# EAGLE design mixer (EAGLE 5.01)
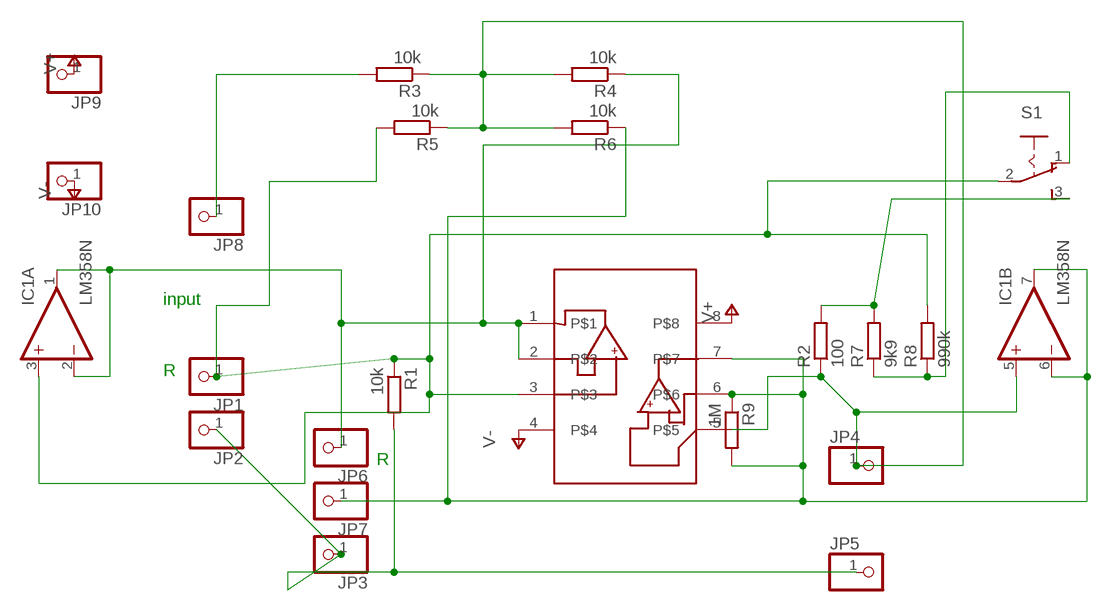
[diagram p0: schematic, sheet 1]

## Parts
IC1  LM358N  [DIL08]
JP1  PINHD-1X1  [1X01]
JP2  PINHD-1X1  [1X01]
JP3  PINHD-1X1  [1X01]
JP4  PINHD-1X1  [1X01]
JP5  PINHD-1X1  [1X01]
JP6  PINHD-1X1  [1X01]
JP7  PINHD-1X1  [1X01]
JP8  PINHD-1X1  [1X01]
JP9  PINHD-1X1  [1X01]
JP10  PINHD-1X1  [1X01]
R1  10k  R-EU_0207/10  [0207/10]
R2  100  R-EU_0207/10  [0207/10]
R3  10k  R-EU_0207/10  [0207/10]
R4  10k  R-EU_0207/10  [0207/10]
R5  10k  R-EU_0207/10  [0207/10]
R6  10k  R-EU_0207/10  [0207/10]
R7  9k9  R-EU_0207/10  [0207/10]
R8  990k  R-EU_0207/10  [0207/10]
R9  1M  R-EU_0204/7  [0204/7]
S1  255SB  [255SB]
U$1  MCP6042SOIC  [SO-08]

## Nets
GND: JP2.1 JP3.1 JP5.1 R1.2
IN_L: JP8.1 R3.2
IN_R: IC1.3(A:+IN) JP1.1 R1.1 R5.2 R8.2 S1.2(P) U$1.3
N$3: R2.2 R7.2 S1.3(S)
N$7: R7.1 R8.1 S1.1(O)
N$8: IC1.5(B:+IN) JP4.1 R2.1 R3.1 R4.2 R5.1 R6.2 U$1.5
OUT_L: IC1.6(B:-IN) IC1.7(B:OUT) JP7.1 R6.1 R9.1 R9.2 U$1.6 U$1.7
OUT_R: IC1.1(A:OUT) IC1.2(A:-IN) JP6.1 R4.1 U$1.1 U$1.2
V+: JP9.1 U$1.8
V-: JP10.1 U$1.4

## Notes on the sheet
- input
- R
- R

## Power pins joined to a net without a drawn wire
V+: IC1.8(P:V+)
V-: IC1.4(P:V-)

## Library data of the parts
IC1 = linear4:LM358: OP AMP
JP1-JP10 = pinhead:PINHD-1X1: PIN HEADER
R1-R9 = rcl-2:R-EU_: RESISTOR, European symbol
S1 = switch:255SB: SLIDING SWITCH distributor Buerklin, 11G810
U$1 = microchip-3:MCP6042

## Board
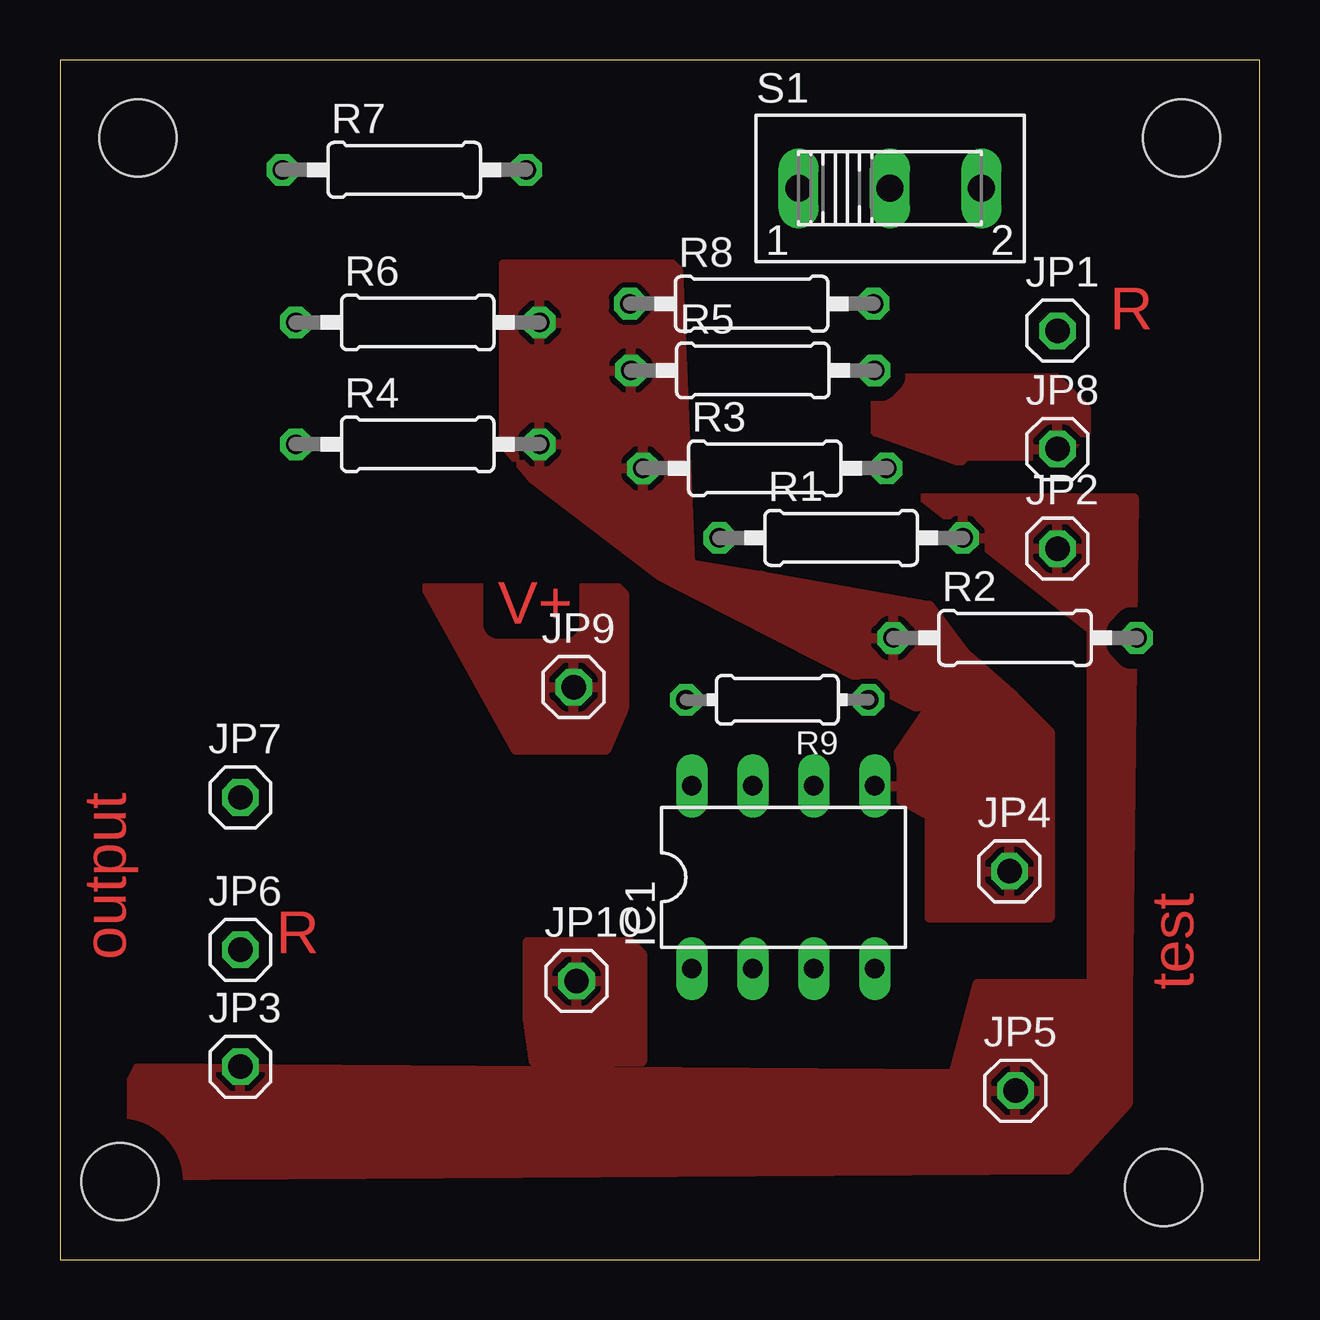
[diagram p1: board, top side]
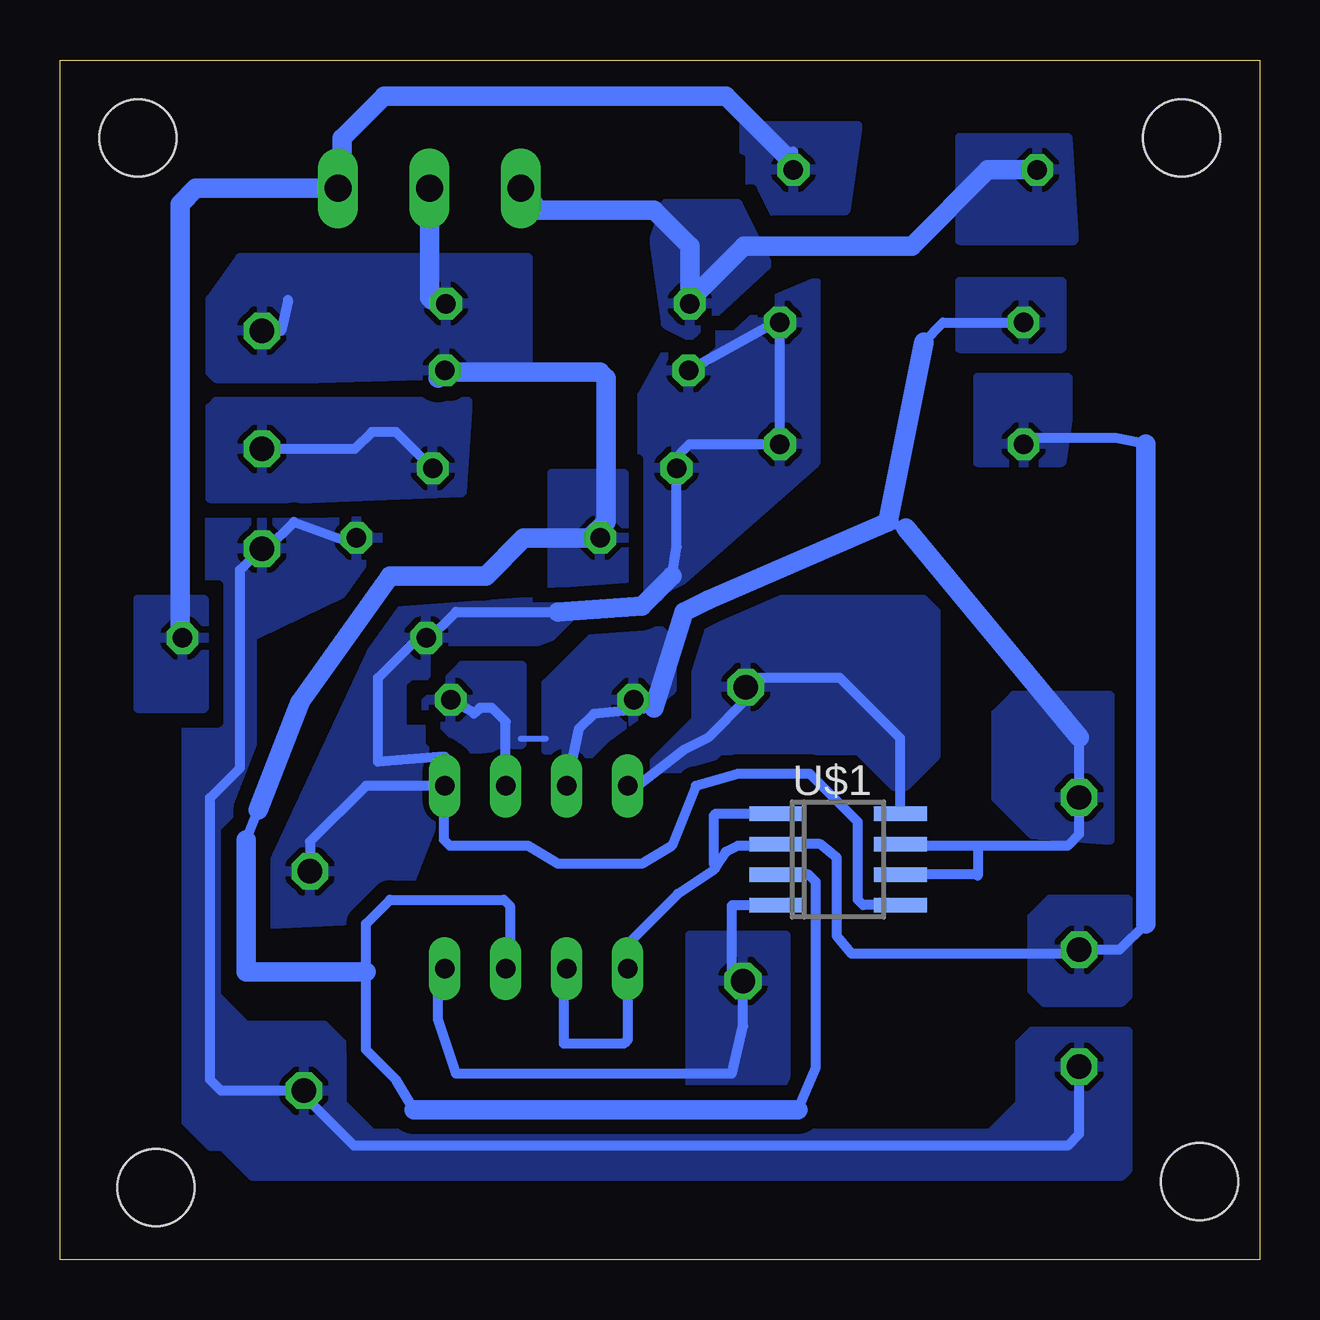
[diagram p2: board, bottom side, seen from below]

Size 50 x 50 mm. Coordinates in mm from the lower left corner, seen from the top.
Outline: 0,0 50,0 50,50 0,50 0,0
Copper layers (1*16): Top 0.035mm / dielectric 1.5mm / Bottom 0.035mm
Design rules "default *": minimum track width 10mil, minimum drill 24mil, track to track 8mil, track to pad 8mil, pad to pad 8mil, via to via 8mil, smd to smd 8mil, copper to edge 40mil, drill to drill 8mil, minimum pad ring 10mil, minimum via ring 8mil, stop-mask expansion 4mil, vias tented up to drill 0mil, thermal gap 10mil
Holes 3.2 mm at 46.75,46.75 46,3 2.5,3.25 3.25,46.75

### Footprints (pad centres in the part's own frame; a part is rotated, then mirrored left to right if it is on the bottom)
DIL08 = drill 0.813 long: 1 -3.81,-3.81; 2 -1.27,-3.81; 3 1.27,-3.81; 4 3.81,-3.81; 5 3.81,3.81; 6 1.27,3.81; 7 -1.27,3.81; 8 -3.81,3.81
1X01 = drill 1.016 octagon: 1 0,0
0207/10 = drill 0.813 octagon: 1 -5.08,0; 2 5.08,0
0204/7 = drill 0.813 octagon: 1 -3.81,0; 2 3.81,0
255SB = drill 1.118 long: 1 -3.81,0; 2 0,0; 3 3.81,0
SO-08 = smd 0.6 x 2.2: 1 -1.905,-2.6; 2 -0.635,-2.6; 3 0.635,-2.6; 4 1.905,-2.6; 5 1.905,2.6; 6 0.635,2.6; 7 -0.635,2.6; 8 -1.905,2.6

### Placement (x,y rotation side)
IC1  30.15,15.93 0 top
JP1  41.58,38.71 0 top
JP2  41.58,29.63 0 top
JP3  7.52,8.04 0 top
JP4  39.58,16.18 0 top
JP5  39.83,7.04 0 top
JP6  7.52,12.91 0 top
JP7  7.52,19.26 0 top
JP8  41.58,33.79 0 top
JP9  21.41,23.86 0 top
JP10  21.53,11.61 0 top
R1  32.56,30.08 0 top
R2  39.81,25.91 0 top
R3  29.38,32.98 0 top
R4  14.91,33.98 0 top
R5  28.88,37.06 0 top
R6  14.91,39.06 0 top
R7  14.35,45.42 0 top
R8  28.83,39.84 0 top
R9  29.9,23.33 180 top
S1  34.6,44.65 0 top
U$1  17.57,16.68 270 bottom

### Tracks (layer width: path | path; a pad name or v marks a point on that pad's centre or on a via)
GND
  Bottom 0.406: JP3.1 7.52,5.23 8,4.75 37.75,4.75 40,7 39.96,7.04 JP5.1 43.29,7.04 43.75,7.5 43.75,19.25 42.5,20.5 42.5,28.75 41.62,29.63 JP2.1 41.37,29.63 40.25,30.75 37.5,29.75 37.64,29.89 R1.2
  pour Top (isolate 0.61, rank 2): 43,11.5 43,26.25 36,31.75 44.75,31.75 44.5,11 44.5,6.5 42,3.75 3,3.5 3,7.5 3.25,8 37.25,7.75 38.25,11.5
  pour Bottom (isolate 0.61, rank 3): 5.5,9.5 9.5,9.5 10,9 10,6.5 11.25,5.25 37,5.25 38.25,6.5 38.25,9 39,9.75 42.25,9.75 43.5,11 43.5,18 42,19.5 42,26 36.75,28.5 36.75,30.75 44.75,31.75 44.75,28.75 43.75,27.75 43.75,24.25 44.75,23.25 44.75,5.75 43.75,4.75 43.25,4.75 42,3.5 5.75,3.5 5.5,3.75
IN_L
  Bottom 0.406: JP8.1 37.71,33.79 37,34.5 36,34.5 34.46,32.96 | 34.46,32.96 34.25,32.75 | R3.2 34.46,32.96
  pour Bottom (isolate 0.61): 33,35.75 43.5,35.75 43.75,35.5 43.75,31.75 39.5,31.75 33.25,32
  pour Top (isolate 0.61, rank 2): 34,34.5 34,36.25 34.5,36.75 41.5,36.75 42.75,35.5 42.75,34.5 41.75,33.5 41.5,33.5 37.75,33.5 37.5,33.25
IN_R
  Bottom 0.406: U$1.3 18.8,16.05 18.5,15.75 18.5,8 19.25,6.25 | 35.25,6.25 36,7.5 37.25,8.75 37.25,12 37.25,14 36.25,15 31.5,15 31.25,14.75 31.25,12.5 31.5,12.25 31.42,12.17 IC1.3 | JP1.1 40.79,38.71 40.5,40 | 30.67,30.08 R1.1 | 42.25,17.5 41.75,18.75
  Bottom 0.813: 19.25,6.25 35.25,6.25 | 41.75,18.75 40,23.25 36.25,28.5 32.25,28.5 30.67,30.08 27.92,30.08 27.25,30.75 27.25,36.75 27.5,37 34,37 | 42.25,17.5 42.25,12 37.25,12 | 34,37 33.96,37.04 R5.2 | 34,37 34.25,36.75 | S1.2 34.6,40.1 34.5,40 34,40 33.91,39.91 R8.2
  pour Bottom (isolate 0.61): 30.5,41.75 42.5,41.75 43.75,40 43.75,37 43.5,36.75 39.25,36.75 30.5,37
  pour Bottom (isolate 0.61): 26.5,32.75 29.5,32.75 29.5,28 26.5,28
N$3
  Bottom 0.406: R7.2 19.43,46.18 | 45,25.75 44.89,25.86 R2.2
  Bottom 0.813: 45,40 45,25.75 | 45,40 45,41 | R7.2 19.43,45.68 22.25,48.5 36.5,48.5 38.25,46.75 38.25,45.25 38.5,45 38.41,44.91 S1.3 44.35,44.65 45,44 45,40
  pour Bottom (isolate 0.61, rank 2): 44,27.5 46.75,27.5 46.75,27.25 46.75,23 44,23 44,23.25
  pour Bottom (isolate 0.61, rank 2): 16.75,47.25 21.5,47.25 21.5,46.25 21.25,46.25 21.25,43.75 17.25,43.75
N$7
  Bottom 0.813: R7.1 11.33,45.42 14.5,42.25 21.5,42.25 23.75,40 R8.1 23.75,42.25 25.25,43.75 30.25,43.75 30.25,44 30.79,44.54 S1.1
  pour Bottom (isolate 0.61): 20.5,41.5 21.75,44 24.75,44 25.25,42.5 24.75,39 23.75,38.5
  pour Bottom (isolate 0.61, rank 2): 8,46.75 12.5,46.75 12.5,42.5 7.75,42.5 7.75,42.75
N$8
  Bottom 0.406: U$1.5 16.52,14.78 16.75,15 16.75,18.25 18.75,20.25 21.75,20.25 23.5,19.75 24.5,17.25 25.75,16.5 29.25,16.5 30.5,17.25 33.75,17.25 34,17.5 34,19.25 34.25,19.5 34.01,19.74 IC1.5 | R5.1 20.19,39.06 20,39.25 19.99,39.24 R6.2 R4.2 | R4.2 19.99,33.76 20,33.75 | R4.2 23.77,33.98 24.5,33.25 24.3,33.05 R3.1 24.3,29.7 24.5,28.5 | 34.73,25.77 34.75,25.75 | 34.73,25.77 R2.1 34.73,26.23 34.75,26.25 36.75,24.25 36.75,20.75 33.96,20.96 IC1.5 | 29.25,27 33.5,27 34.73,25.77 | JP4.1 39.58,17.42 37.25,19.75 33.75,19.75 33.76,19.74 IC1.5
  Bottom 0.813: 24.5,28.5 25.75,27.25 29.25,27
  pour Top (isolate 0.61): 37.75,25.25 39.75,23.5 41.25,22 41.25,14.25 36.25,14.25 36.25,18.5 34,19.75
  pour Top: 18.5,41.5 25.5,41.5 25.75,41.25 26.25,29 29.25,28.5 36.25,27.25 37.75,25.25 35.75,23 25,28.5 19.75,32.5 18.5,34
  pour Bottom (isolate 0.61, rank 2): 18.5,40.75 24.5,38.25 25.75,36 25.75,29 26,27.75 36.25,27 41.25,16.25 41.25,14 36,14.25 33.75,20 35.25,23.25 34.25,24.25 24.75,27.75 18.5,33.25
OUT_L
  Bottom 0.254: 29.75,21.7 30.8,21.7
  Bottom 0.406: 7.52,21.77 JP7.1 7.52,17.73 8,17.25 11.75,17.25 | 14.75,30.5 15.5,30.75 | IC1.7 28.38,22.12 27.75,22.75 25.25,23 25.17,23.08 R9.2 | IC1.6 31.42,22.42 32,23 32.5,23 32.71,22.79 | 32.71,22.79 32.75,22.75 | 32.71,22.79 R9.1 | R6.1 13.19,39.06 14,38.25 | U$1.7 14.56,17.32 14.5,17.25 11.75,17.25 | U$1.6 11.79,16.05 11.75,16 11.75,17.25
  Bottom 0.813: 7.52,21.77 14.75,30.5 | 25.25,23 24,27 23,27.5 15.5,30.75 14,38.25
  pour Bottom (isolate 0.61): 6.25,23.5 10.25,23.5 11,22.75 11,19.25 9.5,17.75 6.25,17.5
  pour Bottom (rank 2): 8.25,40.75 12.5,40.75 12.5,38 8.25,38
  pour Bottom (isolate 0.61): 24.5,23.75 24.5,25.75 25,26.25 27.5,26.25 29.75,24 29.75,21.25 29,20.5 28.5,20.5 27.25,21.75
  pour Bottom (isolate 0.61): 30.75,21.5 30.75,24.75 33.25,24.75 34.75,23.25 34.75,23 33,21.25
OUT_R
  Bottom 0.406: 4.75,14 5.84,12.91 JP6.1 7.84,12.91 8,12.75 17,12.75 17.62,13.5 17.62,16.75 18.32,17.32 U$1.2 20.18,17.32 20.25,17.25 21.75,17.25 22.25,17 22.64,16.42 | 4.75,34 6,34.25 10,34.25 9.83,34.08 R4.1 | 22.64,16.42 22.75,16.25 24.25,15.25 26.25,13.25 26.25,11.75 26.34,11.84 IC1.1 26.34,9.16 26.5,9 29,9 29,12.25 IC1.2 | U$1.1 22.66,18.59 22.75,18.5 22.75,16.5 22.67,16.42 22.64,16.42
  Bottom 0.813: 4.75,14 4.75,34
  pour Bottom (isolate 0.61): 5.5,15 8.75,15 9.5,14.25 9.5,11.25 9,10.75 5.75,10.75 5.5,11
  pour Bottom (rank 2): 8,35 8,36.75 11.75,36.75 11.75,33.25 8.25,33.25
V+
  Bottom 0.406: U$1.8 14.97,21.72 17.5,24.25 21,24.25 21.41,23.84 | 21.41,23.84 21.5,23.75 | 21.41,23.84 JP9.1 21.41,23.34 23,21.75 24,21.25 26.25,19.5 26.34,19.59 IC1.8
  pour Top (isolate 0.61, rank 2): 15.25,28 23.25,28 23.5,27.75 23.5,23 22.75,21.25 19,21.25
  pour Bottom (isolate 0.61): 16,27.5 23,27.5 23.5,27 23.5,22.5 25.5,20.5 23.25,20.5 22.5,21.25 16.75,21.25 15.25,19.75 14.75,19.75 13.5,21 13.5,27 14,27.5
V-
  Bottom 0.406: IC1.4 33.96,12.04 34.25,11.75 34.25,10 33.5,7.75 22,7.75 21.53,9.72 JP10.1 21.64,11.61 21.75,11.5 22,11.75 22,14.75 21.98,14.78 U$1.4
  pour Top (isolate 0.61, rank 2): 19.5,13.25 23.75,13.25 24.25,12.75 24.25,8.25 19.75,8.25 19.5,10
  pour Bottom (isolate 0.61): 19.75,13.5 23.75,13.5 23.75,12.75 23.75,7.25 19.75,7.25

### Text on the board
Top: R | V+ | R | output | test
